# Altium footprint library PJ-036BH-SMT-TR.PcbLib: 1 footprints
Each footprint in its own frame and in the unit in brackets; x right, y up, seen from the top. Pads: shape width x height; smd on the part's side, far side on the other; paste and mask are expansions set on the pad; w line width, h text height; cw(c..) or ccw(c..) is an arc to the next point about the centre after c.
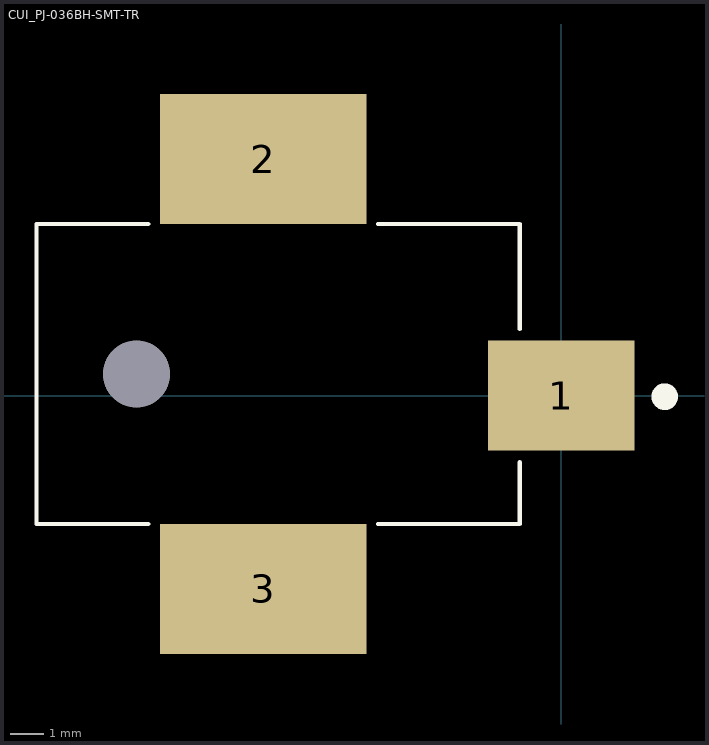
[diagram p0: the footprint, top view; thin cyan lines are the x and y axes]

## CUI_PJ-036BH-SMT-TR [mm]
pads (4):
  rect 4.4x3.3 smd: 1(0,0)
  rect 6.2x3.9 smd: 2(-8.95,7.1) 3(-8.95,-5.8)
  round 2 hole 2 unplated: ""(-12.75,0.65)
Top Overlay:
  circle w0.4: c3.104,-0.03 r0.2
  lines w0.127: -12.4,-3.85 -15.75,-3.85 -15.75,5.15 -12.4,5.15 ; -5.5,-3.85 -1.25,-3.85 -1.25,-2 ; -5.5,5.15 -1.25,5.15 -1.25,2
